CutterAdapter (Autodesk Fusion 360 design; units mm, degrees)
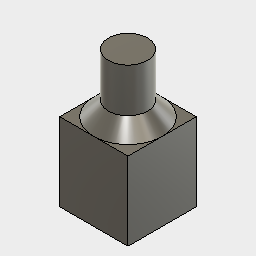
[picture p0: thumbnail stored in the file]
sketch "Sketch2" plane through (0, 0, 0) normal (0, 1, 0) x axis (1, 0, 0)
  line L1 (-7, -7) -> (7, -7)
  line L2 (-7, 7) -> (-7, -7)
  line L3 (7, 7) -> (-7, 7)
  line L4 (7, -7) -> (7, 7)
  line L5 (-7, 7) -> (7, -7)
  line L6 (7, 7) -> (-7, -7)
  point P3 (-7, -7)
  point P4 (-7, 7)
  dimension "d3" distance L2 L4 = 14
  dimension "d4" distance P3 P4 = 14
extrude "Extrude1" sketch "Sketch2" profile of L1 L2 L3 L4 blind 16
sketch "Sketch3" plane through (0, 16, 0) normal (0, 1, 0) x axis (-1, 0, 0)
  line L1 (7, -7) -> (-7, -7)
  line L2 (7, 7) -> (7, -7)
  line L3 (-7, 7) -> (7, 7)
  line L4 (-7, -7) -> (-7, 7)
  circle C1 centre (0, 0) radius 4
  dimension "d7" diameter C1 = 8
extrude "Extrude2" sketch "Sketch3" profile of C1 blind 12
chamfer "Chamfer1" distance 3
sketch "Sketch4" plane through (0, 0, 0) normal (0, -1, 0) x axis (1, 0, 0)
  line L1 (7, -7) -> (-7, -7)
  line L2 (7, 7) -> (7, -7)
  line L3 (-7, 7) -> (7, 7)
  line L4 (-7, -7) -> (-7, 7)
  circle C1 centre (0, 0) radius 4.3
  dimension "d11" diameter C1 = 8.6
hole "Hole1" HoleDepth 12 HoleDiameter 8.6 TipAngle 118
